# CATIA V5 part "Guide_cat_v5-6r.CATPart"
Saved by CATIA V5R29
Part number: Guide
Bounding box of the stored display mesh (mm): x -25 to 25, y -50 to 25, z -10 to 10
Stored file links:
  C:\Users\CADCIM 00\Desktop\New folder (2)\c16\New folder\Slide Curve\Guide_cat_v5-6r.CATPart
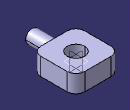
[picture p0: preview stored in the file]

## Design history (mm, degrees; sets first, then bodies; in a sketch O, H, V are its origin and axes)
Body1 (main body)
  Sketch1 on xy-plane, origin (0, 0, 0), H (1, 0, 0), V (0, 1, 0)
    circle A1 centre (0, 0) radius 10
    line L1 (-25, 25) -> (25, 25)
    line L2 (25, 25) -> (25, -25)
    line L3 (25, -25) -> (-25, -25)
    line L4 (-25, -25) -> (-25, 25)
    radius A1 = 10
    length L4 = 50
    length L3 = 50
    distance V L4 = 25
    distance L3 H = 25
    horizontal: L1 H, L3 H
    vertical: L2 V, L4 V
  Pad1: profile Sketch1, direction (0, 0, 1), length 10, mirrored extent
  Sketch2 on face of Pad1 from Sketch1.L3, origin (0, -25, 0), H (1, 0, 0), V (0, 0, 1)
    circle A1 centre (0, 0) radius 7.5
    point P1 (0, 0)
    reference projected line E1 (-25, 10) -> (25, 10) from edge [face of Pad1 from Sketch1.L3 | end face of Pad1]
    radius A1 = 7.5
    distance E1 P1 = 10
    coincidence: P1 V
  Pad2: profile Sketch2, direction (0, -1, 0), length 25
  Fillet1: radius 10, on edge [face of Pad1 from Sketch1.L2 | face of Pad1 from Sketch1.L3]; edge [face of Pad1 from Sketch1.L3 | face of Pad1 from Sketch1.L4]; edge [face of Pad1 from Sketch1.L1 | face of Pad1 from Sketch1.L2]; edge [face of Pad1 from Sketch1.L4 | face of Pad1 from Sketch1.L1]
  Fillet2: radius 2, on edge [face of Pad1 from Sketch1.L3 | face of Pad2 from Sketch2.A1]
